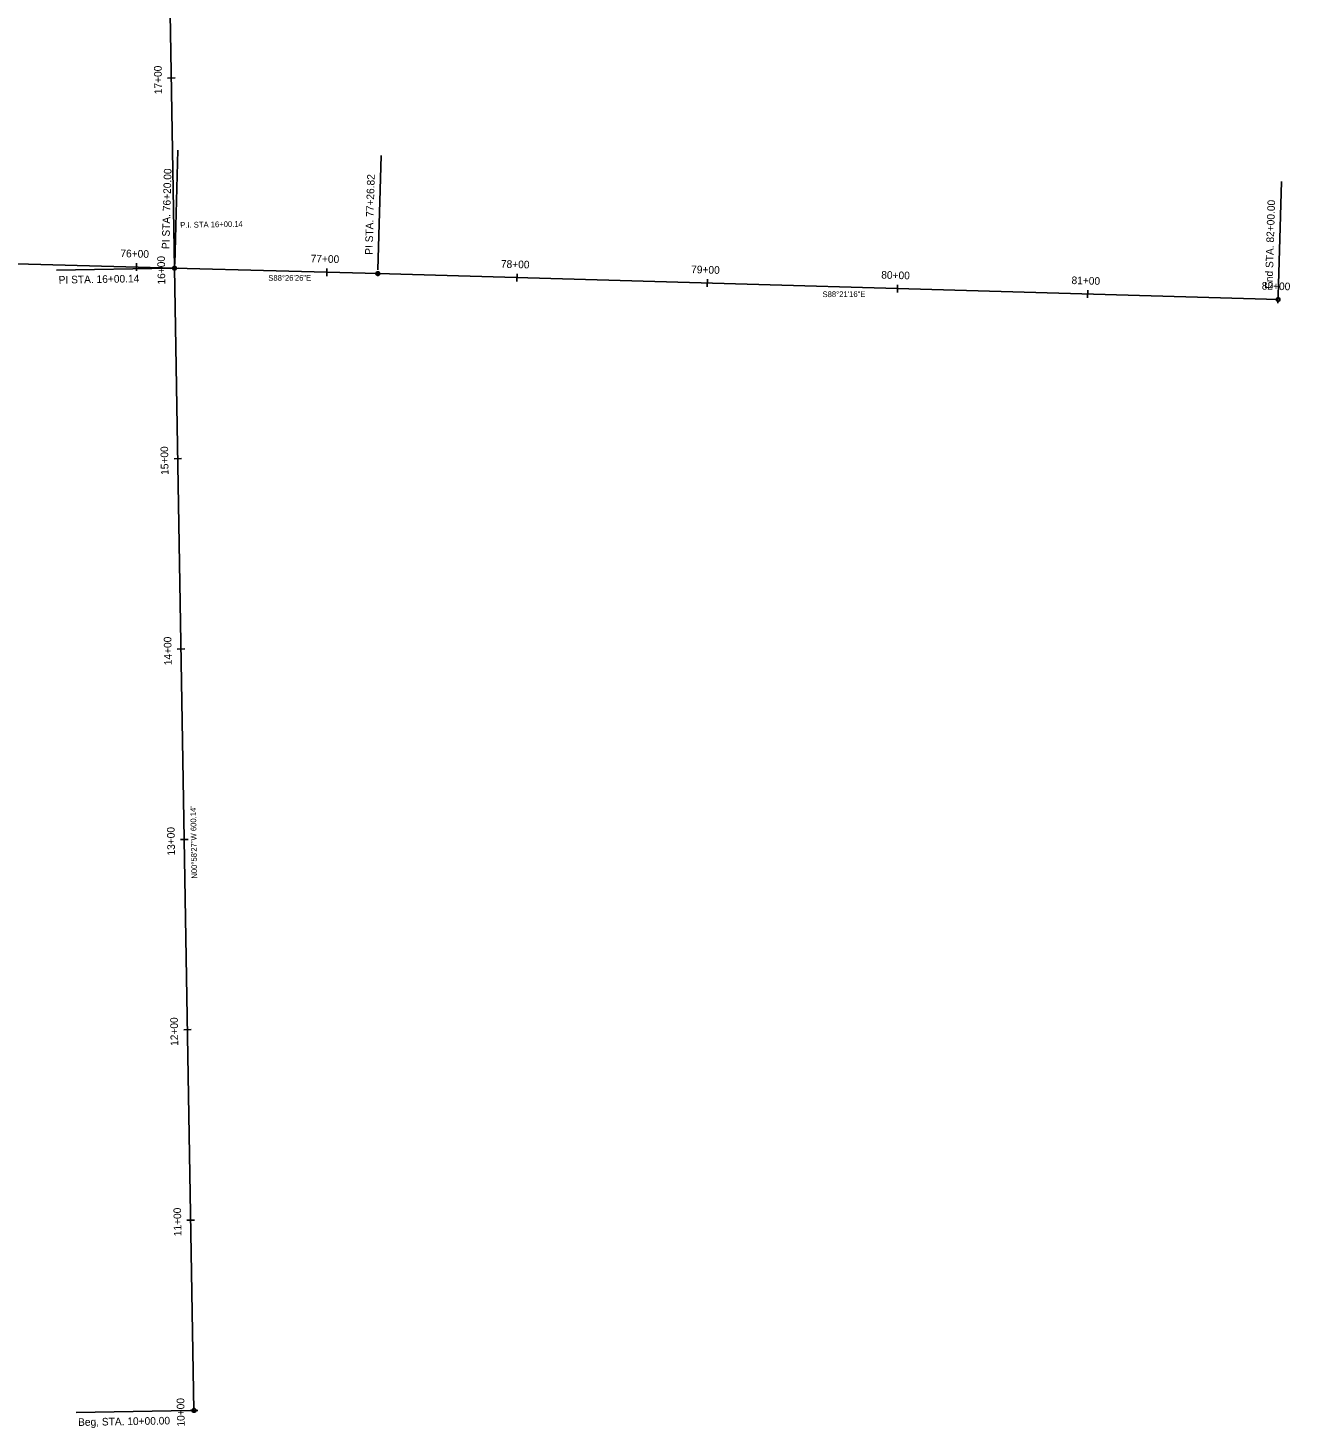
# Model space of a CAD drawing. Extents: x 925213 to 926427, y 852880 to 858734.
# Drawn here: x 925764 to 926427, y 852880 to 853615 of the extents above; entities that cross this region are included whole.
import ezdxf

# ---------------------------------------------------------------- set-up
doc = ezdxf.new("R2010")
doc.units = 0
for name, color, linetype in [('BaselineSurvey', 7, 'Continuous'), ('CurveData_dp', 7, 'Continuous'), ('CurveDataLabel_dp', 7, 'Continuous'), ('Default', 7, 'Continuous'), ('StationTicL_dp', 7, 'Continuous'), ('TextBLStation', 7, 'Continuous'), ('TextCurveData', 7, 'Continuous')]:
    doc.layers.add(name, color=color, linetype=linetype)

# ---------------------------------------------------------------- blocks, each defined once
blk = doc.blocks.new('PI')
at = {"layer": 'Default'}
blk.add_lwpolyline([(0, 9.8), (-8.5, -4.9), (8.5, -4.9), (0, 9.8)], dxfattribs=at)
blk.add_circle((0, 0), 0.602, dxfattribs=at)
blk = doc.blocks.new('FDOTStationTicL')
at = {"layer": 'StationTicL_dp'}
blk.add_line((0, -0.5), (0, 0.5), dxfattribs=at)
blk = doc.blocks.new('AeccTickCircle')
at = {"layer": 'Default'}
blk.add_circle((0, 0), 1, dxfattribs=at)

msp = doc.modelspace()

# ---------------------------------------------------------------- linework, layer by layer
at = {"layer": 'BaselineSurvey'}
for points in [[(925851.59, 852889.09), (925841.39, 853489.14), (925787.13, 856680.25), (925776.51, 857315.66)], [(925221.62, 853506.01), (925841.39, 853489.14), (925948.17, 853486.23), (926421.16, 853472.64)]]:
    msp.add_lwpolyline(points, dxfattribs=at)
at = {"layer": 'CurveDataLabel_dp'}
for p, q in [((925841.44, 853491.14), (925843.08, 853551.12)), ((925948.22, 853488.23), (925949.85, 853548.21)), ((926421.21, 853474.64), (926422.94, 853534.62)), ((925839.39, 853489.11), (925779.4, 853488.09)), ((925849.59, 852889.05), (925789.6, 852888.03))]:
    msp.add_line(p, q, dxfattribs=at)

# ---------------------------------------------------------------- block references
at = {"layer": 'CurveData_dp', "xscale": 0.10878433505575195, "yscale": 0.10878433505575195}
for p in [(925841.39, 853489.14), (925841.39, 853489.14), (925948.17, 853486.23)]:
    msp.add_blockref('PI', p, dxfattribs=at)
at = {"layer": 'CurveDataLabel_dp'}
for p, rotation in [((925841.39, 853489.14), -1.5594444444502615), ((925841.39, 853489.14), 90.97411168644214), ((925948.17, 853486.23), -1.5594444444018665), ((926421.16, 853472.64), -1.6455555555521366), ((925851.59, 852889.09), 90.97411168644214)]:
    msp.add_blockref('AeccTickCircle', p, dxfattribs=dict(at, rotation=rotation))
at = {"layer": 'TextBLStation'}
for p, xscale, yscale, rotation in [((925839.69, 853588.99), 4, 4, 90.97411168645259), ((925821.39, 853489.68), 4, 4, -1.5594444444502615), ((925841.39, 853489), 4, 4, 90.97411168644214), ((925921.36, 853486.96), 4, 3.999999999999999, -1.5594444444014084), ((926021.32, 853484.13), 3.9999999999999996, 3.9999999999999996, -1.6455555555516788), ((926121.27, 853481.26), 3.9999999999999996, 3.9999999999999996, -1.6455555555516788), ((926221.23, 853478.39), 3.9999999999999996, 3.9999999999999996, -1.6455555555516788), ((926321.19, 853475.52), 3.9999999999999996, 3.9999999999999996, -1.6455555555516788), ((926421.15, 853472.64), 3.9999999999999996, 3.9999999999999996, -1.6455555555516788), ((926421.16, 853472.64), 3.9999999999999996, 3.9999999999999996, -1.6455555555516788), ((925843.09, 853389.01), 4, 4, 90.97411168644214), ((925844.79, 853289.03), 4, 4, 90.97411168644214), ((925846.49, 853189.04), 4, 4, 90.97411168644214), ((925848.19, 853089.06), 4, 4, 90.97411168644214), ((925849.89, 852989.07), 4, 4, 90.97411168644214), ((925851.59, 852889.09), 4, 4, 90.97411168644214)]:
    msp.add_blockref('FDOTStationTicL', p, dxfattribs=dict(at, xscale=xscale, yscale=yscale, rotation=rotation))

# ---------------------------------------------------------------- texts
at = {"layer": 'CurveDataLabel_dp'}
for s, rotation, p in [('PI STA. 76+20.00', 88.44056, (925838.65, 853499.09)), ('PI STA. 77+26.82', 88.44056, (925945.42, 853496.08)), ('End STA. 82+00.00', 88.35444, (926418.3, 853478.14)), ('PI STA. 16+00.14', 0.97411, (925780.52, 853480.98)), ('Beg, STA. 10+00.00', 0.97411, (925790.72, 852880.92))]:
    msp.add_text(s, height=4, rotation=rotation, dxfattribs=at).set_placement(p)
at = {"layer": 'TextBLStation'}
for s, height, rotation, p in [('17+00', 4, 90.97411, (925834.83, 853580.51)), ('P.I. STA 16+00.14', 3, 0.99139, (925844.37, 853510.3)), ('76+00', 4, 358.44056, (925812.87, 853494.93)), ('16+00', 4, 90.97411, (925836.53, 853480.53)), ('77+00', 4, 358.44056, (925912.84, 853492.21)), ('78+00', 4, 358.35444, (926012.8, 853489.39)), ('79+00', 4, 358.35444, (926112.76, 853486.52)), ('80+00', 4, 358.35444, (926212.64, 853483.65)), ('81+00', 4, 358.35444, (926312.6, 853480.77)), ('82+00', 4, 358.35444, (926412.56, 853477.9)), ('82+00', 4, 358.35444, (926412.56, 853477.9)), ('15+00', 4, 90.97411, (925838.23, 853380.54)), ('14+00', 4, 90.97411, (925839.93, 853280.55)), ('13+00', 4, 90.97411, (925841.63, 853180.57)), ('12+00', 4, 90.97411, (925843.33, 853080.58)), ('11+00', 4, 90.97411, (925845.03, 852980.6)), ('10+00', 4, 90.97411, (925846.73, 852880.61))]:
    msp.add_text(s, height=height, rotation=rotation, dxfattribs=at).set_placement(p)
at = {"layer": 'TextCurveData'}
for s, rotation, p in [('S88°26\'26"E', 0.33776, (925890.65, 853482.44)), ('S88°21\'16"E', 0.33776, (926181.85, 853473.89)), ('N00°58\'27"W 600.14\'', 90.97411, (925853.29, 853168.44))]:
    msp.add_text(s, height=3, rotation=rotation, dxfattribs=at).set_placement(p)

doc.saveas('drawing.dxf')
